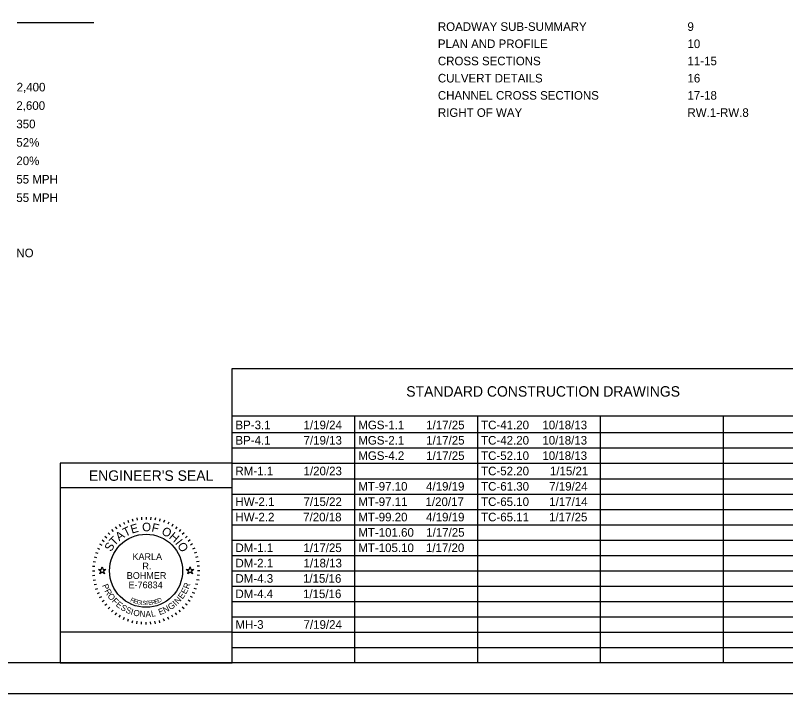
# Model space of a CAD drawing. Extents: x 0 to 34, y 0 to 22.
# Drawn here: x 7.72 to 20.26, y 0 to 11.04 of the extents above; entities that cross this region are included whole.
import ezdxf

# ---------------------------------------------------------------- set-up
doc = ezdxf.new("R2010")
doc.units = 0
for name, color, linetype in [('Default', 7, 'Continuous'), ('SH_Border', 7, 'Continuous'), ('SH_Cut_Line', 7, 'Continuous'), ('SH_Data', 7, 'Continuous'), ('SH_Text', 7, 'Continuous')]:
    doc.layers.add(name, color=color, linetype=linetype)

msp = doc.modelspace()

# ---------------------------------------------------------------- linework, layer by layer
at = {"layer": 'Default'}
for points in [[(9.074, 2.02), (9.121, 2.02), (9.135, 2.065), (9.149, 2.02), (9.196, 2.02), (9.158, 1.992), (9.173, 1.948), (9.135, 1.975), (9.097, 1.948), (9.112, 1.992)], [(10.504, 2.02), (10.551, 2.02), (10.565, 2.065), (10.579, 2.02), (10.626, 2.02), (10.588, 1.992), (10.603, 1.948), (10.565, 1.975), (10.527, 1.948), (10.542, 1.992)]]:
    msp.add_lwpolyline(points, close=True, dxfattribs=at)
at = {"layer": 'SH_Border'}
msp.add_lwpolyline([(1.5, 21.5), (33.5, 21.5), (33.5, 0.5), (1.5, 0.5)], close=True, dxfattribs=at)
at = {"layer": 'SH_Cut_Line'}
msp.add_lwpolyline([(0, 0), (34, 0), (34, 22), (0, 22)], close=True, dxfattribs=at)
at = {"layer": 'SH_Data'}
for p, q in [((9, 10.922), (7.75, 10.922)), ((11.25, 5.292), (24.7, 5.292)), ((11.25, 0.5), (11.25, 5.292)), ((11.25, 0.5), (11.25, 5.292)), ((11.25, 4.521), (24.7, 4.521)), ((13.25, 0.5), (13.25, 4.521)), ((15.25, 0.5), (15.25, 4.521)), ((17.25, 0.5), (17.25, 4.521)), ((19.25, 0.5), (19.25, 4.521)), ((11.25, 4.25), (22.975, 4.25)), ((11.25, 4), (22.975, 4)), ((11.25, 3.75), (8.45, 3.75)), ((8.45, 3.75), (8.45, 0.5)), ((11.25, 3.75), (22.975, 3.75)), ((11.25, 0.5), (11.25, 3.75)), ((11.25, 3.5), (24.7, 3.5)), ((11.25, 3.35), (8.45, 3.35)), ((11.25, 3.25), (24.7, 3.25)), ((11.25, 3), (24.7, 3)), ((9.48, 2.793), (9.497, 2.757)), ((9.551, 2.822), (9.564, 2.785)), ((9.624, 2.845), (9.634, 2.807)), ((9.698, 2.862), (9.705, 2.822)), ((9.774, 2.872), (9.777, 2.832)), ((9.85, 2.875), (9.85, 2.835)), ((9.926, 2.872), (9.923, 2.832)), ((10.002, 2.862), (9.995, 2.822)), ((10.076, 2.845), (10.066, 2.807)), ((10.149, 2.822), (10.136, 2.785)), ((10.22, 2.793), (10.203, 2.757)), ((9.288, 2.67), (9.313, 2.64)), ((9.348, 2.717), (9.371, 2.684)), ((9.413, 2.758), (9.433, 2.723)), ((10.287, 2.758), (10.267, 2.723)), ((10.352, 2.717), (10.329, 2.684)), ((10.412, 2.67), (10.387, 2.64)), ((11.25, 2.75), (24.7, 2.75)), ((9.18, 2.562), (9.21, 2.537)), ((9.231, 2.619), (9.26, 2.59)), ((10.469, 2.619), (10.44, 2.59)), ((10.52, 2.562), (10.49, 2.537)), ((9.092, 2.438), (9.127, 2.418)), ((9.133, 2.502), (9.166, 2.479)), ((10.567, 2.502), (10.534, 2.479)), ((10.608, 2.438), (10.573, 2.418)), ((11.25, 2.5), (24.7, 2.5)), ((9.028, 2.299), (9.065, 2.286)), ((9.057, 2.37), (9.093, 2.353)), ((10.643, 2.37), (10.607, 2.353)), ((10.672, 2.299), (10.635, 2.286)), ((8.988, 2.152), (9.028, 2.145)), ((9.005, 2.226), (9.043, 2.216)), ((10.695, 2.226), (10.657, 2.216)), ((10.712, 2.152), (10.672, 2.145)), ((11.25, 2.25), (24.7, 2.25)), ((8.978, 2.076), (9.018, 2.073)), ((10.722, 2.076), (10.682, 2.073)), ((8.975, 2), (9.015, 2)), ((8.978, 1.924), (9.018, 1.927)), ((10.722, 1.924), (10.682, 1.927)), ((10.725, 2), (10.685, 2)), ((11.25, 2), (24.7, 2)), ((8.988, 1.848), (9.028, 1.855)), ((9.005, 1.774), (9.043, 1.784)), ((10.695, 1.774), (10.657, 1.784)), ((10.712, 1.848), (10.672, 1.855)), ((9.028, 1.701), (9.065, 1.714)), ((9.057, 1.63), (9.093, 1.647)), ((10.643, 1.63), (10.607, 1.647)), ((10.672, 1.701), (10.635, 1.714)), ((11.25, 1.75), (24.7, 1.75)), ((9.092, 1.563), (9.127, 1.583)), ((9.133, 1.498), (9.166, 1.521)), ((10.567, 1.498), (10.534, 1.521)), ((10.608, 1.563), (10.573, 1.583)), ((9.18, 1.438), (9.21, 1.463)), ((9.231, 1.381), (9.26, 1.41)), ((10.469, 1.381), (10.44, 1.41)), ((10.52, 1.438), (10.49, 1.463)), ((11.25, 1.5), (24.7, 1.5)), ((9.288, 1.33), (9.313, 1.36)), ((9.348, 1.283), (9.371, 1.316)), ((9.413, 1.242), (9.433, 1.277)), ((10.287, 1.242), (10.267, 1.277)), ((10.352, 1.283), (10.329, 1.316)), ((10.412, 1.33), (10.387, 1.36)), ((9.48, 1.207), (9.497, 1.243)), ((9.551, 1.178), (9.564, 1.215)), ((9.624, 1.155), (9.634, 1.193)), ((9.698, 1.138), (9.705, 1.178)), ((9.774, 1.128), (9.777, 1.168)), ((9.85, 1.125), (9.85, 1.165)), ((9.926, 1.128), (9.923, 1.168)), ((10.002, 1.138), (9.995, 1.178)), ((10.076, 1.155), (10.066, 1.193)), ((10.149, 1.178), (10.136, 1.215)), ((10.22, 1.207), (10.203, 1.243)), ((11.25, 1.25), (24.7, 1.25)), ((11.25, 1), (24.7, 1)), ((11.25, 0.75), (24.7, 0.75)), ((11.25, 0.5), (8.45, 0.5))]:
    msp.add_line(p, q, dxfattribs=at)
msp.add_lwpolyline([(11.25, 0.5), (11.25, 1), (8.45, 1), (8.45, 0.5)], close=True, dxfattribs=at)
msp.add_circle((9.85, 2), 0.595, dxfattribs=at)

# ---------------------------------------------------------------- texts
for s, height, p in [("ENGINEER'S SEAL", 0.17, (8.918, 3.465)), ('KARLA', 0.11, (9.628, 2.175)), ('R.', 0.11, (9.79, 2.022)), ('BOHMER', 0.11, (9.535, 1.868)), ('E-76834', 0.11, (9.564, 1.715))]:
    msp.add_text(s, height=height, dxfattribs=at).set_placement(p)
for s, height, rotation, p in [('E', 0.14, 15.7571, (9.618, 2.604)), ('O', 0.14, 359.7812, (9.785, 2.644)), ('F', 0.14, 347.4362, (9.931, 2.642)), ('A', 0.14, 36.4747, (9.413, 2.478)), ('T', 0.14, 25.7167, (9.512, 2.552)), ('O', 0.14, 332.2586, (10.09, 2.602)), ('T', 0.14, 46.4344, (9.338, 2.396)), ('H', 0.14, 319.9136, (10.213, 2.536)), ('I', 0.14, 308.367, (10.316, 2.448)), ('S', 0.14, 57.1924, (9.278, 2.301)), ('O', 0.14, 303.1491, (10.352, 2.409)), ('P', 0.1, 291.494, (9.132, 1.762)), ('R', 0.1, 69.2322, (10.542, 1.695)), ('R', 0.1, 298.7311, (9.169, 1.672)), ('E', 0.1, 54.758, (10.443, 1.531)), ('E', 0.1, 61.9951, (10.498, 1.61)), ('O', 0.1, 306.4666, (9.215, 1.588)), ('F', 0.1, 314.7068, (9.284, 1.498)), ('E', 0.1, 321.4393, (9.348, 1.435)), ('R', 0.07, 334.487, (9.587, 1.505)), ('E', 0.07, 341.04, (9.641, 1.48)), ('G', 0.07, 347.4752, (9.691, 1.462)), ('I', 0.07, 353.7858, (9.759, 1.447)), ('S', 0.07, 356.8926, (9.786, 1.443)), ('T', 0.07, 3.0061, (9.836, 1.439)), ('E', 0.07, 6.0117, (9.889, 1.441)), ('R', 0.07, 11.9184, (9.942, 1.447)), ('E', 0.07, 17.6836, (10, 1.46)), ('D', 0.07, 23.3052, (10.051, 1.477)), ('I', 0.1, 43.287, (10.337, 1.421)), ('N', 0.1, 47.0224, (10.37, 1.451)), ('S', 0.1, 328.6764, (9.424, 1.375)), ('S', 0.1, 335.9134, (9.506, 1.327)), ('I', 0.1, 343.1505, (9.591, 1.29)), ('E', 0.1, 20.0742, (10.071, 1.277)), ('N', 0.1, 27.3113, (10.154, 1.308)), ('G', 0.1, 35.0469, (10.248, 1.357)), ('O', 0.1, 346.8859, (9.634, 1.275)), ('N', 0.1, 355.1261, (9.739, 1.252)), ('A', 0.1, 2.8617, (9.842, 1.244)), ('L', 0.1, 10.0987, (9.939, 1.249))]:
    msp.add_text(s, height=height, rotation=rotation, dxfattribs=at).set_placement(p)
at = {"layer": 'SH_Text'}
for s, height, p in [('ROADWAY SUB-SUMMARY', 0.14, (14.601, 10.792)), ('9', 0.14, (18.665, 10.792)), ('PLAN AND PROFILE', 0.14, (14.601, 10.512)), ('10', 0.14, (18.665, 10.512)), ('CROSS SECTIONS', 0.14, (14.601, 10.232)), ('11-15', 0.14, (18.665, 10.232)), ('CULVERT DETAILS', 0.14, (14.601, 9.952)), ('16', 0.14, (18.665, 9.952)), ('2,400', 0.14, (7.742, 9.806)), ('CHANNEL CROSS SECTIONS', 0.14, (14.601, 9.672)), ('17-18', 0.14, (18.665, 9.672)), ('2,600', 0.14, (7.737, 9.506)), ('RIGHT OF WAY', 0.14, (14.601, 9.392)), ('RW.1-RW.8', 0.14, (18.665, 9.392)), ('350', 0.14, (7.737, 9.206)), ('52%', 0.14, (7.737, 8.906)), ('20%', 0.14, (7.737, 8.606)), ('55 MPH', 0.14, (7.737, 8.306)), ('55 MPH', 0.14, (7.737, 8.006)), ('NO', 0.14, (7.737, 7.106)), ('STANDARD CONSTRUCTION DRAWINGS', 0.17, (14.086, 4.836)), ('BP-3.1', 0.14, (11.305, 4.305)), ('1/19/24', 0.14, (12.414, 4.305)), ('MGS-1.1', 0.14, (13.305, 4.305)), ('1/17/25', 0.14, (14.411, 4.305)), ('TC-41.20', 0.14, (15.305, 4.305)), ('10/18/13', 0.14, (16.302, 4.305)), ('BP-4.1', 0.14, (11.305, 4.055)), ('7/19/13', 0.14, (12.414, 4.055)), ('MGS-2.1', 0.14, (13.305, 4.055)), ('1/17/25', 0.14, (14.411, 4.055)), ('TC-42.20', 0.14, (15.305, 4.055)), ('10/18/13', 0.14, (16.302, 4.055)), ('MGS-4.2', 0.14, (13.305, 3.805)), ('1/17/25', 0.14, (14.411, 3.805)), ('TC-52.10', 0.14, (15.305, 3.805)), ('10/18/13', 0.14, (16.302, 3.805)), ('RM-1.1', 0.14, (11.305, 3.555)), ('1/20/23', 0.14, (12.414, 3.555)), ('TC-52.20', 0.14, (15.305, 3.555)), ('1/15/21', 0.14, (16.426, 3.555)), ('MT-97.10', 0.14, (13.305, 3.305)), ('4/19/19', 0.14, (14.409, 3.305)), ('TC-61.30', 0.14, (15.305, 3.305)), ('7/19/24', 0.14, (16.414, 3.305)), ('HW-2.1', 0.14, (11.305, 3.055)), ('7/15/22', 0.14, (12.413, 3.055)), ('MT-97.11', 0.14, (13.305, 3.055)), ('1/20/17', 0.14, (14.4, 3.055)), ('TC-65.10', 0.14, (15.305, 3.055)), ('1/17/14', 0.14, (16.414, 3.055)), ('HW-2.2', 0.14, (11.305, 2.805)), ('7/20/18', 0.14, (12.408, 2.805)), ('MT-99.20', 0.14, (13.305, 2.805)), ('4/19/19', 0.14, (14.409, 2.805)), ('TC-65.11', 0.14, (15.305, 2.805)), ('1/17/25', 0.14, (16.411, 2.805)), ('MT-101.60', 0.14, (13.305, 2.555)), ('1/17/25', 0.14, (14.411, 2.555)), ('DM-1.1', 0.14, (11.305, 2.305)), ('1/17/25', 0.14, (12.411, 2.305)), ('MT-105.10', 0.14, (13.305, 2.305)), ('1/17/20', 0.14, (14.407, 2.305)), ('DM-2.1', 0.14, (11.305, 2.055)), ('1/18/13', 0.14, (12.414, 2.055)), ('DM-4.3', 0.14, (11.305, 1.805)), ('1/15/16', 0.14, (12.405, 1.805)), ('DM-4.4', 0.14, (11.305, 1.555)), ('1/15/16', 0.14, (12.405, 1.555)), ('MH-3', 0.14, (11.305, 1.055)), ('7/19/24', 0.14, (12.414, 1.055))]:
    msp.add_text(s, height=height, dxfattribs=at).set_placement(p)

doc.saveas('drawing.dxf')
